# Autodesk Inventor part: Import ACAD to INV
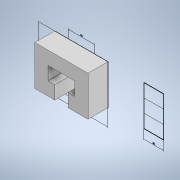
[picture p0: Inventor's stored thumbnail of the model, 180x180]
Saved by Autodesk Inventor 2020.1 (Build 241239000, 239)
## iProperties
Created: 2019-11
Part Number: Import ACAD to INV
Material: Generic
Document SubType Name: Modeling
Designer: Synergysoft Dell02
Density: 1 g/cm^3
Appearance: Default
Author: Synergysoft Dell02
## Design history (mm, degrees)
node "Import ACAD to INV_1.dwg"
sketch "Sketch1"
  geometry: L1 (50, 0)-(80, 0) reference; L2 (50, 20)-(50, 0) reference; L3 (60, 20)-(50, 20) reference; L4 (60, 40)-(60, 20) reference; L5 (20, 40)-(60, 40) reference; L6 (20, 20)-(20, 40) reference; L7 (30, 20)-(20, 20) reference; L8 (30, 0)-(30, 20) reference; L9 (0, 0)-(30, 0) reference; L10 (0, 60)-(0, 0) reference; L11 (80, 60)-(0, 60) reference; L12 (80, 0)-(80, 60) reference; L13 (133.795, 0)-(163.797, 0) reference; L14 (163.797, 0)-(163.797, 60) reference; L15 (163.797, 60)-(133.795, 60) reference; L16 (133.795, 60)-(133.795, 0) reference
extrude "Extrusion1" new body sketch "Sketch1" distance "d0" = 30; taper "d1" = 0 deg
body "Solid1"
